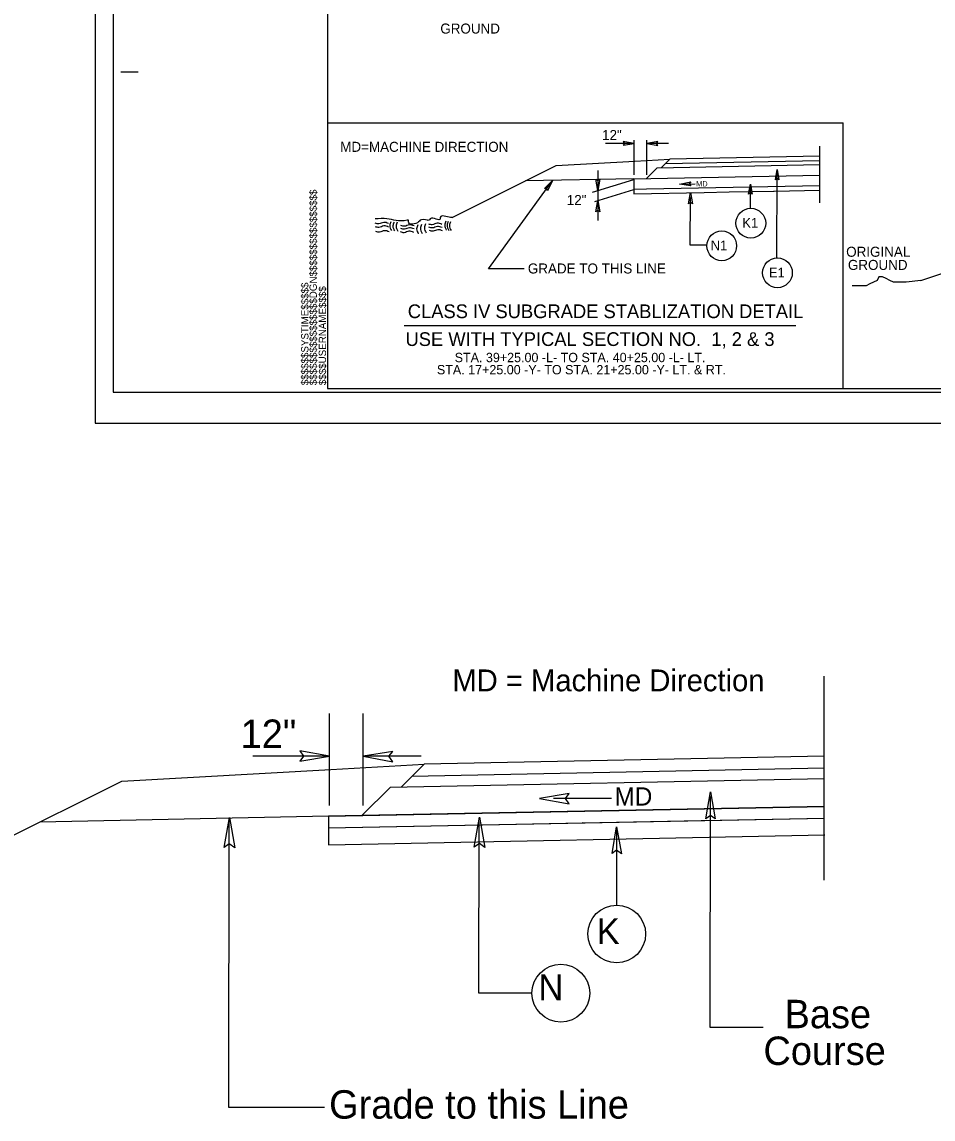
# Model space of a CAD drawing. Extents: x 2176024 to 2177225, y 75947 to 76635.
# Drawn here: x 2176620.9 to 2176725.6, y 76374.5 to 76500.6 of the extents above; entities that cross this region are included whole.
import ezdxf

# ---------------------------------------------------------------- set-up
doc = ezdxf.new("R2010")
doc.units = 0
for name, color, linetype in [('Old_Level_1', 7, 'Continuous'), ('Old_Level_10', 7, 'Continuous'), ('Old_Level_11', 7, 'Continuous'), ('Old_Level_2', 7, 'Continuous'), ('Old_Level_3', 7, 'Continuous'), ('Old_Level_5', 7, 'Continuous'), ('Prop Pavement Schedule Description CELL', 7, 'Continuous'), ('Sheet Cutting Line CELL', 7, 'Continuous'), ('Sheet Plot Border Inside CELL', 7, 'Continuous'), ('Sheet Plot Border Outside CELL', 7, 'Continuous'), ('Sheet Typical CELL', 7, 'Continuous'), ('Typical ID Circle CELL', 7, 'Continuous'), ('Typical Shoulder Slope CELL', 7, 'Continuous'), ('Typical Slope Point Local CELL', 7, 'Continuous'), ('Typical Terminator CELL', 7, 'Continuous'), ('Typical Text General CELL', 7, 'Continuous'), ('Typical Text Label CELL', 7, 'Continuous')]:
    doc.layers.add(name, color=color, linetype=linetype)

msp = doc.modelspace()

# ---------------------------------------------------------------- linework, layer by layer
at = {"layer": 'Old_Level_1'}
msp.add_line((2176664.79, 76465.7), (2176709.81, 76465.7), dxfattribs=at)
at = {"layer": 'Old_Level_10'}
for p, q in [((2176655.99, 76489.02), (2176715.25, 76489.02)), ((2176715.25, 76458.48), (2176715.25, 76489.02)), ((2176670.32, 76478.11), (2176682.28, 76484.09)), ((2176600.43, 76397.41), (2176632.34, 76413.36))]:
    msp.add_line(p, q, dxfattribs=at)
at = {"layer": 'Old_Level_11'}
for p, q in [((2176691.24, 76486.63), (2176687.94, 76486.63)), ((2176691.24, 76483.04), (2176691.24, 76487)), ((2176692.68, 76483.04), (2176692.68, 76487)), ((2176695.18, 76486.63), (2176692.68, 76486.63)), ((2176712.55, 76479.82), (2176712.55, 76486.31)), ((2176686.42, 76481.03), (2176691.19, 76482.48)), ((2176686.7, 76479.96), (2176691.19, 76481.35)), ((2176696.44, 76481.97), (2176698.22, 76482)), ((2176713.05, 76401.96), (2176713.05, 76425.43)), ((2176656.23, 76410.55), (2176656.23, 76421.11)), ((2176660.07, 76410.56), (2176660.07, 76421.11)), ((2176656.23, 76416.21), (2176647.42, 76416.21)), ((2176666.74, 76416.21), (2176660.07, 76416.21)), ((2176688.63, 76411.37), (2176681.95, 76411.37))]:
    msp.add_line(p, q, dxfattribs=at)
for points in [[(2176689.96, 76486.42), (2176691.24, 76486.63), (2176689.96, 76486.86), (2176690.12, 76486.63)], [(2176693.96, 76486.84), (2176692.68, 76486.63), (2176693.96, 76486.4), (2176693.8, 76486.63)], [(2176697.73, 76481.78), (2176696.44, 76481.97), (2176697.72, 76482.23), (2176697.56, 76481.99)], [(2176652.81, 76415.65), (2176656.23, 76416.21), (2176652.81, 76416.83), (2176653.24, 76416.21)], [(2176663.49, 76416.77), (2176660.07, 76416.21), (2176663.49, 76415.59), (2176663.05, 76416.21)], [(2176683.75, 76411.92), (2176680.33, 76411.36), (2176683.75, 76410.74), (2176683.32, 76411.36)]]:
    msp.add_lwpolyline(points, close=True, dxfattribs=at)
at = {"layer": 'Old_Level_2'}
for p, q in [((2176682.28, 76484.09), (2176691.29, 76484.6)), ((2176693.87, 76483.84), (2176692.63, 76482.6)), ((2176695.32, 76484.82), (2176694.34, 76483.85)), ((2176691.19, 76482.57), (2176678.75, 76482.33)), ((2176632.34, 76413.36), (2176656.37, 76414.7)), ((2176667.1, 76415.3), (2176664.5, 76412.7)), ((2176663.23, 76412.68), (2176659.94, 76409.39)), ((2176656.1, 76409.31), (2176622.91, 76408.65))]:
    msp.add_line(p, q, dxfattribs=at)
for points in [[(2176644.11, 76405.71), (2176644.71, 76409.17), (2176645.32, 76405.69), (2176644.7, 76406.14)], [(2176672.85, 76405.76), (2176673.45, 76409.22), (2176674.06, 76405.74), (2176673.45, 76406.18)]]:
    msp.add_lwpolyline(points, close=True, dxfattribs=at)
for points in [[(2176670.32, 76478.11), (2176670.12, 76478.13), (2176668.95, 76478.13), (2176668.95, 76477.97), (2176667.79, 76477.97), (2176667.62, 76477.8), (2176667.46, 76477.8), (2176666.63, 76477.8), (2176666.46, 76477.63), (2176665.3, 76477.63), (2176665.3, 76477.8), (2176665.13, 76477.8), (2176662.8, 76477.97), (2176661.47, 76477.97)], [(2176662.98, 76477.43), (2176662.44, 76477.56), (2176661.88, 76477.39), (2176661.47, 76477.47)], [(2176663.27, 76477.64), (2176663.14, 76477.2), (2176663.33, 76476.62)], [(2176663.63, 76477.6), (2176663.5, 76477.16), (2176663.68, 76476.58)], [(2176664, 76477.59), (2176663.87, 76477.14), (2176664.06, 76476.56)], [(2176666.79, 76477.33), (2176666.66, 76476.88), (2176666.85, 76476.3)], [(2176667.26, 76477.38), (2176667.13, 76476.93), (2176667.32, 76476.36)], [(2176669.13, 76477.33), (2176668.59, 76477.47), (2176668.03, 76477.3), (2176667.62, 76477.37)], [(2176669.59, 76477.7), (2176669.46, 76477.25), (2176669.64, 76476.67)], [(2176669.87, 76477.68), (2176669.74, 76477.23), (2176669.92, 76476.65)], [(2176670.13, 76477.64), (2176670, 76477.2), (2176670.18, 76476.62)], [(2176663, 76477.02), (2176662.46, 76477.15), (2176661.9, 76476.98), (2176661.49, 76477.06)], [(2176663.06, 76476.48), (2176662.52, 76476.61), (2176661.96, 76476.44), (2176661.55, 76476.51)], [(2176665.89, 76476.42), (2176665.35, 76476.55), (2176664.79, 76476.38), (2176664.38, 76476.46)], [(2176665.93, 76477.15), (2176665.39, 76477.28), (2176664.83, 76477.11), (2176664.42, 76477.19)], [(2176665.93, 76476.81), (2176665.39, 76476.94), (2176664.83, 76476.78), (2176664.42, 76476.85)], [(2176666.37, 76477.27), (2176666.23, 76476.82), (2176666.42, 76476.24)], [(2176669.15, 76476.96), (2176668.61, 76477.09), (2176668.05, 76476.92), (2176667.64, 76477)], [(2176669.21, 76476.59), (2176668.67, 76476.72), (2176668.11, 76476.55), (2176667.7, 76476.63)]]:
    msp.add_spline(points, degree=3, dxfattribs=at)
at = {"layer": 'Old_Level_3'}
for p, q in [((2176712.55, 76485.17), (2176695.32, 76484.82)), ((2176691.29, 76484.6), (2176695.32, 76484.82)), ((2176693.87, 76483.84), (2176712.55, 76484.21)), ((2176694.78, 76484.29), (2176694.34, 76483.85)), ((2176695.32, 76484.82), (2176694.78, 76484.29)), ((2176712.55, 76484.64), (2176694.78, 76484.29)), ((2176694.78, 76484.29), (2176694.78, 76484.29)), ((2176691.19, 76482.57), (2176712.55, 76483)), ((2176691.19, 76482.48), (2176691.19, 76481.35)), ((2176691.19, 76481.35), (2176691.19, 76480.85)), ((2176702.14, 76481.07), (2176702.15, 76481.09)), ((2176702.15, 76481.07), (2176707.25, 76481.17)), ((2176702.15, 76481.09), (2176702.15, 76481.07)), ((2176707.33, 76481.17), (2176712.55, 76481.27)), ((2176712.55, 76481.27), (2176712.55, 76481.78)), ((2176713.05, 76416.22), (2176667.1, 76415.3)), ((2176656.37, 76414.7), (2176667.1, 76415.3)), ((2176667.1, 76415.3), (2176665.67, 76413.88)), ((2176713.05, 76414.83), (2176665.67, 76413.88)), ((2176663.23, 76412.68), (2176713.05, 76413.67)), ((2176665.67, 76413.88), (2176664.5, 76412.7)), ((2176665.67, 76413.88), (2176665.67, 76413.88)), ((2176656.1, 76409.31), (2176713.05, 76410.45)), ((2176656.1, 76409.31), (2176656.1, 76407.97)), ((2176713.05, 76409.1), (2176713.05, 76410.45)), ((2176656.09, 76409.06), (2176656.09, 76406.05)), ((2176656.1, 76407.97), (2176713.08, 76409.11)), ((2176685.3, 76408.55), (2176685.31, 76408.61)), ((2176685.31, 76408.61), (2176685.32, 76408.55)), ((2176685.32, 76408.55), (2176698.93, 76408.82)), ((2176699.13, 76408.83), (2176713.05, 76409.1)), ((2176656.09, 76406.05), (2176713.12, 76407.19))]:
    msp.add_line(p, q, dxfattribs=at)
for points in [[(2176712.55, 76481.78), (2176692.63, 76481.38), (2176691.19, 76481.35)], [(2176707.25, 76481.17), (2176707.33, 76481.17)], [(2176691.19, 76480.85), (2176699.27, 76481.01), (2176702.14, 76481.07)], [(2176713.05, 76410.45), (2176659.94, 76409.39), (2176656.1, 76409.31)], [(2176656.1, 76407.97), (2176677.63, 76408.4), (2176685.3, 76408.55)], [(2176698.93, 76408.82), (2176699.13, 76408.83)]]:
    msp.add_lwpolyline(points, dxfattribs=at)
at = {"layer": 'Old_Level_5'}
for p, q in [((2176707.64, 76473.47), (2176707.66, 76483.43)), ((2176674.48, 76472.22), (2176681.77, 76482.28)), ((2176697.68, 76474.95), (2176697.69, 76480.42)), ((2176699.57, 76474.95), (2176697.68, 76474.95)), ((2176678.6, 76472.22), (2176674.48, 76472.22)), ((2176699.96, 76385.04), (2176700, 76411.59)), ((2176644.65, 76375.85), (2176644.7, 76408.97)), ((2176673.39, 76388.99), (2176673.42, 76408.63)), ((2176679.47, 76388.99), (2176673.39, 76388.99)), ((2176706.05, 76385.04), (2176699.96, 76385.04)), ((2176655.64, 76375.85), (2176644.65, 76375.85))]:
    msp.add_line(p, q, dxfattribs=at)
at = {"layer": 'Prop Pavement Schedule Description CELL'}
msp.add_line((2176687.05, 76483.51), (2176687.05, 76477.77), dxfattribs=at)
for points in [[(2176680.91, 76481.47), (2176681.85, 76482.38), (2176681.27, 76481.19), (2176681.18, 76481.46)], [(2176687.28, 76482.52), (2176687.05, 76481.22), (2176686.83, 76482.53), (2176687.06, 76482.36)], [(2176686.83, 76478.78), (2176687.05, 76480.07), (2176687.28, 76478.77), (2176687.05, 76478.93)], [(2176697.47, 76479.7), (2176697.7, 76481), (2176697.93, 76479.7), (2176697.7, 76479.86)]]:
    msp.add_lwpolyline(points, close=True, dxfattribs=at)
at = {"layer": 'Sheet Cutting Line CELL'}
for p, q in [((2176629.27, 76630.48), (2176629.27, 76454.48)), ((2176629.27, 76454.48), (2176898.71, 76454.48))]:
    msp.add_line(p, q, dxfattribs=at)
at = {"layer": 'Sheet Plot Border Inside CELL'}
msp.add_lwpolyline([(2176897.99, 76626.88), (2176631.35, 76626.88), (2176631.35, 76458.07), (2176897.99, 76458.07)], close=True, dxfattribs=at)
at = {"layer": 'Sheet Plot Border Outside CELL'}
msp.add_lwpolyline([(2176898.71, 76630.48), (2176629.27, 76630.48), (2176629.27, 76454.48), (2176898.71, 76454.48)], close=True, dxfattribs=at)
at = {"layer": 'Sheet Typical CELL'}
for p, q in [((2176632.23, 76494.88), (2176634.23, 76494.88)), ((2176655.99, 76458.48), (2176655.99, 76458.48)), ((2176655.99, 76458.48), (2176655.99, 76458.48)), ((2176655.99, 76458.48), (2176655.99, 76458.48)), ((2176655.99, 76458.48), (2176655.99, 76458.48)), ((2176655.99, 76458.48), (2176655.99, 76458.48)), ((2176655.99, 76458.48), (2176655.99, 76458.48))]:
    msp.add_line(p, q, dxfattribs=at)
msp.add_lwpolyline([(2176895.99, 76626.48), (2176655.99, 76626.48), (2176655.99, 76458.48), (2176895.99, 76458.48)], close=True, dxfattribs=at)
msp.add_lwpolyline([(2176661.99, 76458.48), (2176661.99, 76458.48)], dxfattribs=at)
at = {"layer": 'Typical ID Circle CELL'}
for p, q in [((2176704.58, 76479.17), (2176704.58, 76481.79)), ((2176689.22, 76399.11), (2176689.22, 76407.88))]:
    msp.add_line(p, q, dxfattribs=at)
for centre, radius in [((2176704.63, 76477.47), 1.71), ((2176701.29, 76474.87), 1.71), ((2176707.69, 76471.77), 1.71), ((2176689.22, 76395.79), 3.32), ((2176689.22, 76395.79), 3.32), ((2176682.8, 76388.99), 3.32)]:
    msp.add_circle(centre, radius, dxfattribs=at)
at = {"layer": 'Typical Shoulder Slope CELL'}
msp.add_line((2176724.15, 76470.9), (2176733.1, 76473.89), dxfattribs=at)
at = {"layer": 'Typical Slope Point Local CELL'}
msp.add_lwpolyline([(2176724.15, 76470.9), (2176722.48, 76470.7), (2176722.06, 76470.7), (2176721.43, 76470.7), (2176721.02, 76470.7), (2176720.6, 76470.9), (2176720.18, 76471.11), (2176719.76, 76471.32), (2176719.35, 76471.32), (2176719.14, 76470.9), (2176718.72, 76470.7), (2176718.3, 76470.49), (2176717.88, 76470.28), (2176717.47, 76470.28), (2176717.05, 76470.28), (2176716.63, 76470.28), (2176716.29, 76470.28)], dxfattribs=at)
at = {"layer": 'Typical Terminator CELL'}
for points in [[(2176707.45, 76482.47), (2176707.65, 76483.63), (2176707.86, 76482.47), (2176707.65, 76482.61)], [(2176704.38, 76480.81), (2176704.58, 76481.97), (2176704.78, 76480.81), (2176704.58, 76480.95)], [(2176699.46, 76409.04), (2176699.99, 76412.12), (2176700.54, 76409.02), (2176699.99, 76409.42)], [(2176688.68, 76405.03), (2176689.21, 76408.11), (2176689.76, 76405.01), (2176689.21, 76405.41)]]:
    msp.add_lwpolyline(points, close=True, dxfattribs=at)

# ---------------------------------------------------------------- texts
at = {"layer": 'Old_Level_2'}
for s, p in [('K ', (2176686.92, 76394.62)), ('N ', (2176680.22, 76388.17))]:
    msp.add_text(s, height=2.975, dxfattribs=at).set_placement(p)
at = {"layer": 'Old_Level_3'}
for s, height, p in [('MD=MACHINE DIRECTION', 1.1533, (2176657.45, 76485.67)), ('12" ', 1.153, (2176683.48, 76479.56)), ('GRADE TO THIS LINE', 1.1533, (2176679.01, 76471.69)), ('MD = Machine Direction', 2.5068, (2176670.34, 76423.68)), ('MD', 2.089, (2176688.97, 76410.55)), ('  Base', 3.264, (2176706.08, 76384.96)), ('Course', 3.264, (2176706.08, 76380.74)), ('Grade to this Line', 3.264, (2176656.17, 76374.57))]:
    msp.add_text(s, height=height, dxfattribs=at).set_placement(p)
msp.add_text('USE WITH TYPICAL SECTION NO.  1, 2 & 3', height=1.5766, rotation=0, dxfattribs=at).set_placement((2176664.95, 76463.36))
at = {"layer": 'Old_Level_5'}
for s, height, p in [('12"', 1.153, (2176687.54, 76487.03)), ('MD', 0.612, (2176698.35, 76481.69)), ('12"', 3.264, (2176646, 76417.17))]:
    msp.add_text(s, height=height, dxfattribs=at).set_placement(p)
at = {"layer": 'Prop Pavement Schedule Description CELL'}
for s, p in [('K1', (2176703.65, 76476.95)), ('N1', (2176700.02, 76474.36)), ('E1', (2176706.71, 76471.24))]:
    msp.add_text(s, height=1.116, dxfattribs=at).set_placement(p)
at = {"layer": 'Sheet Typical CELL'}
for s, p in [('$$$$$$$$$$$$$$$$DGN$$$$$$$$$$$$$$$$', (2176654.76, 76458.85)), ('$$$$$$SYSTIME$$$$$', (2176653.8, 76458.85)), ('$$$$USERNAME$$$$', (2176655.82, 76458.86))]:
    msp.add_text(s, height=0.84, rotation=90, dxfattribs=at).set_placement(p)
at = {"layer": 'Typical Text General CELL'}
for s, p in [('GROUND', (2176668.95, 76499.26)), ('ORIGINAL', (2176715.59, 76473.61)), ('GROUND', (2176715.79, 76472.1))]:
    msp.add_text(s, height=1.153, dxfattribs=at).set_placement(p)
at = {"layer": 'Typical Text Label CELL'}
for s, height, p in [('CLASS IV SUBGRADE STABLIZATION DETAIL', 1.5766, (2176665.21, 76466.56)), ('STA. 39+25.00 -L- TO STA. 40+25.00 -L- LT.', 1.0742, (2176670.6, 76461.5)), ('STA. 17+25.00 -Y- TO STA. 21+25.00 -Y- LT. & RT.', 1.0742, (2176668.56, 76460.1))]:
    msp.add_text(s, height=height, dxfattribs=at).set_placement(p)

doc.saveas('drawing.dxf')
